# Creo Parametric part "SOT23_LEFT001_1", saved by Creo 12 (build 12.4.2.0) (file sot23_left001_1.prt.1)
Units: Custom; MM, KILOGRAM, SECS

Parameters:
  PTC_WM_ITERATION = "0"
  PTC_WM_VERSION = "-.0"
  PTC_WM_LIFECYCLE_STATE = "In Work"
  PTC_WM_LIFECYCLE = "MO_CADDocument"
  PTC_WM_CREATED_BY = "Maximilian Roepper (Z0017RMS: MO)"
  PTC_WM_CREATED_ON = "18-Sep-26 11:36:42 AM"
  PTC_WM_MODIFIED_BY = "Maximilian Roepper (Z0017RMS: MO)"
  PTC_WM_MODIFIED_ON = "18-Sep-26 11:36:46 AM"
  PDMLINKNUMBER = "PDM000071455221"
  PTC_WM_NAME = "sot23_left001_1.prt"
  PTC_WM_NUMBER = "PDM000071455221"

Other parameters: WEIGHT, WEIGHT_FACTOR, WEIGHT_ADD, _MASS_TEMP, _DIFF_TEMP, MC_ERRORS, SUPPLIER

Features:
  1. coordinate system
  2. datum plane "PRT_YZ"
  3. datum plane "PRT_XY"
  4. datum plane "PRT_XZ"
  5. coordinate system
  6. datum axis
  7. datum axis
  8. datum axis
  9. coordinate system
  10. imported feature

Other named items: PRT, SIEMENS_MO, DRW_VIEW_ORG, PRT_X, PRT_Y, PRT_Z, CS0, ROUGH_GROB

Layers: 00_STD_CSYS-KSYS, 01_STD_PLANES-EBENEN, 02_STD_AXES-ACHSEN, 03_STD_CSYS-KSYS, 24_IMPORT_FEAT-IMPORT_KE

Surfaces: 8 plane, 2 cylinder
